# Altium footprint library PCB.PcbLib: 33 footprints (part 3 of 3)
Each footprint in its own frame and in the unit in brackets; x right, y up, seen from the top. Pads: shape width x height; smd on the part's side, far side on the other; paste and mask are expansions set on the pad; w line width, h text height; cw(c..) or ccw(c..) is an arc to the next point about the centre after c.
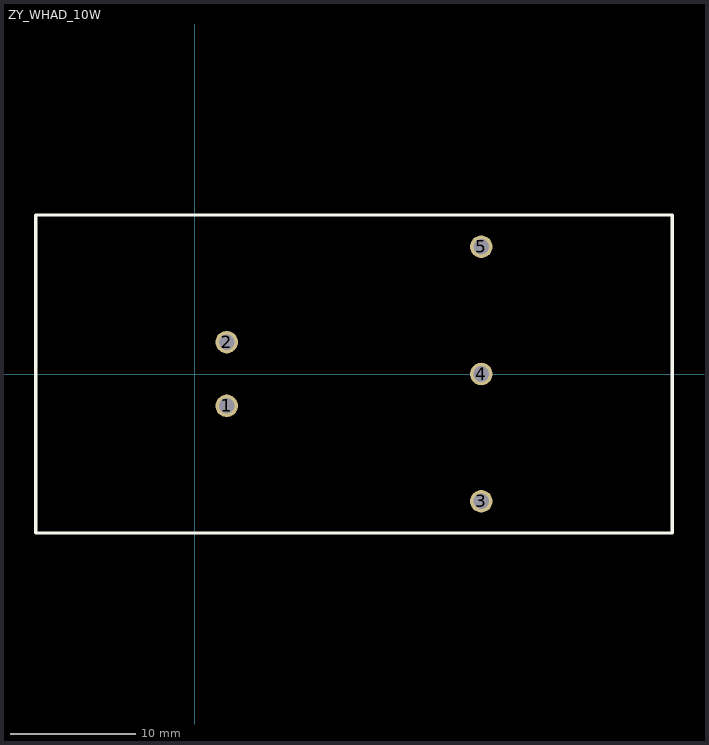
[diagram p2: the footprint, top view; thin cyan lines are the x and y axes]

## ZY_WHAD_10W [mm]
height 1.6
pads (5):
  round 1.8 hole 1.25: 1(2.54,-2.54) 2(2.54,2.54) 3(22.86,-10.16) 4(22.86,0) 5(22.86,10.16)
Top Overlay:
  lines w0.254: -12.7,-12.7 38.1,-12.7 38.1,12.7 -12.7,12.7 -12.7,-12.7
